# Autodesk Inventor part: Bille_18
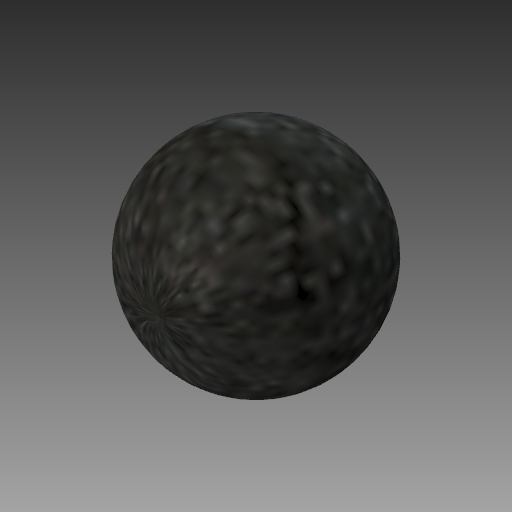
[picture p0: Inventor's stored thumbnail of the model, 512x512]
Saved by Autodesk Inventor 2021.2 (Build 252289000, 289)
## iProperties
Created: 2018-06
Part Number: Bille_18
Material: Acier
Document SubType Name: Modeling
Designer: Fabian Perrée
Density: 7.85 g/cm^3
Appearance: Plaque
Mass: 23.971 g
Surface Area: 10.1788 cm^2
Volume: 3.05363 cm^3
Author: Fabian Perrée
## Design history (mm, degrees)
sketch "Esquisse1"
  geometry: L1 (0, 9)-(0, -9); A1 r 9 centre (0, 0) between (0, -9) and (0, 9); 2 further points
  constraints: 2 coincident, 2 end point, 2 point on circle, 1 centre point, 1 midpoint, 1 vertical
  dimensions: "d2" = 9 radius of A1
revolve "Révolution1" sketch "Esquisse1" stored, may be unused: angle "d3" = 90 deg
node "Solide1"
